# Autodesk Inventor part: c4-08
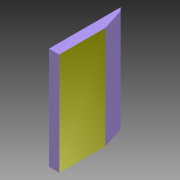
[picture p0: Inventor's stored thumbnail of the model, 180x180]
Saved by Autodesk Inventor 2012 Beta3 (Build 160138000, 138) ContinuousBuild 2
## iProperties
Created: 2010-11
Part Number: c4-08
Material: Default
Document SubType Name: Modeling
Designer: Beta-8540w
Density: 1 g/cm^3
Author: Beta-8540w
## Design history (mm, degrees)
sketch "Sketch1"
  geometry: L1 (0, 0)-(10, 0); L2 (10, 0)-(10, 70); L3 (10, 70)-(0, 70); L4 (0, 70)-(0, 0); L5 (3, 67)-(10, 45); L6 (0, 70)-(3, 67); 1 further point
  constraints: 12 end point, 2 parallel, 2 point on line, 1 horizontal, 1 perpendicular
  dimensions: "d0" = 10 distance of L3.end L2.end; "d1" = 70 distance of L2.end L1.end; "d3" = 25 vertical distance of point (2.045, 70) L5.end; "d6" = 45 deg angle of L4 L6; "d7" = 3 distance from line of L4 L5.start
extrude "Extrusion1" new body sketch "Sketch1" stored distance "d4" = 100; taper "d5" = 0 deg
body "Solid1"
